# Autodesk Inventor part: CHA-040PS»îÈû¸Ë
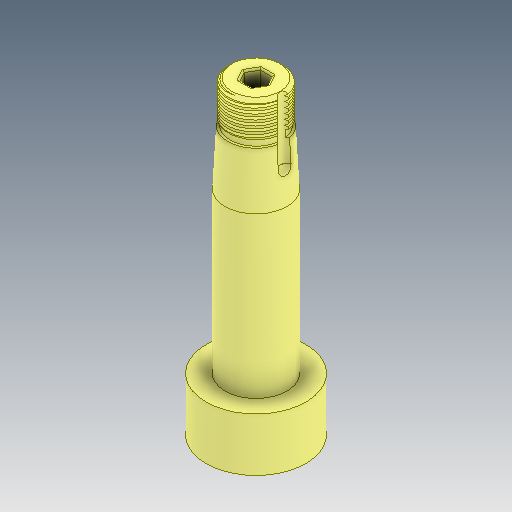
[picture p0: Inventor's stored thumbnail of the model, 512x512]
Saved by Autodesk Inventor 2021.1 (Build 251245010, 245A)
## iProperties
Created: 2021-05
Part Number: CHA-040PS»îÈû¸Ë
Material: Ogólny
Document SubType Name: Modeling
Designer: user
Density: 1 g/cm^3
Appearance: Domyślna
Author: user
Revision Number: ÈÎºÎ
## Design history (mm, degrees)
feature "Ô²½Ç1"
node "Bryła1"
